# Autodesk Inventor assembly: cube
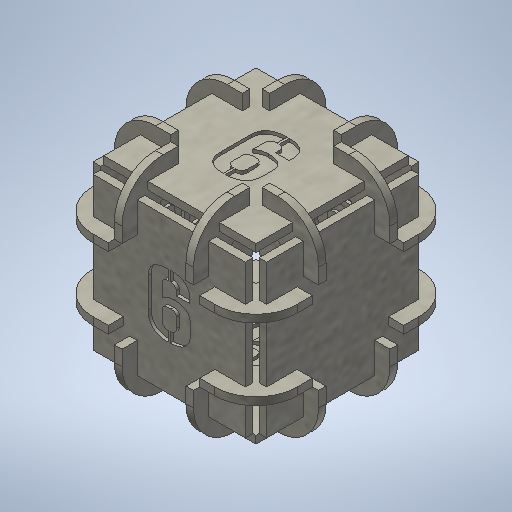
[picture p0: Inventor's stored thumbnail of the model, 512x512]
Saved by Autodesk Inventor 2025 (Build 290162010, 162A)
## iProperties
Created: 2025-02
Part Number: cube
Material: Generisch
Document SubType Name: Assembly
Designer: BennF
Author: BennF
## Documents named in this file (3)
- C:\Users\BennF\OneDrive - Technische Universität Ilmenau\FabAcademy\week03\cube.iam
- C:\Users\BennF\OneDrive - Technische Universität Ilmenau\FabAcademy\week03\square_tile.ipt
- C:\Users\BennF\OneDrive - Technische Universität Ilmenau\FabAcademy\week03\conector_90.ipt
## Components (30 placed, 2 different names)
1. square_tile:1
2. square_tile:2
3. square_tile:3
4. square_tile:4
5. square_tile:5
6. square_tile:6 — Mate:85, Mate:86, Mate:87
7. conector_90:1 — Mate:1, Mate:2, Mate:3
8. conector_90:2 — Mate:4, Mate:5, Mate:6, Mate:34, Mate:35, Mate:36
9. conector_90:3 — Mate:7, Mate:8, Mate:9
10. conector_90:4 — Mate:10, Mate:11, Mate:12, Mate:31, Mate:32, Mate:33
11. conector_90:5 — Mate:13, Mate:14, Mate:15
12. conector_90:6 — Mate:16, Mate:17, Mate:18, Mate:28, Mate:29, Mate:30
13. conector_90:7 — Mate:19, Mate:20, Mate:21
14. conector_90:8 — Mate:22, Mate:23, Mate:24, Mate:25, Mate:26, Mate:27
15. conector_90:9 — Mate:37, Mate:38, Mate:39
16. conector_90:10 — Mate:40, Mate:41, Mate:42
17. conector_90:11 — Mate:43, Mate:44, Mate:45
18. conector_90:12 — Mate:46, Mate:47, Mate:48
19. conector_90:13 — Mate:49, Mate:50, Mate:51
20. conector_90:14 — Mate:52, Mate:53, Mate:54
21. conector_90:15 — Mate:55, Mate:56, Mate:57
22. conector_90:16 — Mate:58, Mate:59, Mate:60
23. conector_90:17 — Mate:61, Mate:62, Mate:63, Mate:85, Mate:86, Mate:87
24. conector_90:18 — Mate:64, Mate:65, Mate:66
25. conector_90:19 — Mate:67, Mate:68, Mate:69
26. conector_90:20 — Mate:70, Mate:71, Mate:72
27. conector_90:21 — Mate:73, Mate:74, Mate:75
28. conector_90:22 — Mate:76, Mate:77, Mate:78
29. conector_90:23 — Mate:79, Mate:80, Mate:81
30. conector_90:24 — Mate:82, Mate:83, Mate:84
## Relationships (87: Mate 87)
- Mate:1: conector_90:1
- Mate:2: conector_90:1
- Mate:3: conector_90:1
- Mate:4: conector_90:2
- Mate:5: conector_90:2
- Mate:6: conector_90:2
- Mate:7: conector_90:3
- Mate:8: conector_90:3
- Mate:9: conector_90:3
- Mate:10: conector_90:4
- Mate:11: conector_90:4
- Mate:12: conector_90:4
- Mate:13: conector_90:5
- Mate:14: conector_90:5
- Mate:15: conector_90:5
- Mate:16: conector_90:6
- Mate:17: conector_90:6
- Mate:18: conector_90:6
- Mate:19: conector_90:7
- Mate:20: conector_90:7
- Mate:21: conector_90:7
- Mate:22: conector_90:8
- Mate:23: conector_90:8
- Mate:24: conector_90:8
- Mate:25: conector_90:8
- Mate:26: conector_90:8
- Mate:27: conector_90:8
- Mate:28: conector_90:6
- Mate:29: conector_90:6
- Mate:30: conector_90:6
- Mate:31: conector_90:4
- Mate:32: conector_90:4
- Mate:33: conector_90:4
- Mate:34: conector_90:2
- Mate:35: conector_90:2
- Mate:36: conector_90:2
- Mate:37: conector_90:9
- Mate:38: conector_90:9
- Mate:39: conector_90:9
- Mate:40: conector_90:10
- Mate:41: conector_90:10
- Mate:42: conector_90:10
- Mate:43: conector_90:11
- Mate:44: conector_90:11
- Mate:45: conector_90:11
- Mate:46: conector_90:12
- Mate:47: conector_90:12
- Mate:48: conector_90:12
- Mate:49: conector_90:13
- Mate:50: conector_90:13
- Mate:51: conector_90:13
- Mate:52: conector_90:14
- Mate:53: conector_90:14
- Mate:54: conector_90:14
- Mate:55: conector_90:15
- Mate:56: conector_90:15
- Mate:57: conector_90:15
- Mate:58: conector_90:16
- Mate:59: conector_90:16
- Mate:60: conector_90:16
- Mate:61: conector_90:17
- Mate:62: conector_90:17
- Mate:63: conector_90:17
- Mate:64: conector_90:18
- Mate:65: conector_90:18
- Mate:66: conector_90:18
- Mate:67: conector_90:19
- Mate:68: conector_90:19
- Mate:69: conector_90:19
- Mate:70: conector_90:20
- Mate:71: conector_90:20
- Mate:72: conector_90:20
- Mate:73: conector_90:21
- Mate:74: conector_90:21
- Mate:75: conector_90:21
- Mate:76: conector_90:22
- Mate:77: conector_90:22
- Mate:78: conector_90:22
- Mate:79: conector_90:23
- Mate:80: conector_90:23
- Mate:81: conector_90:23
- Mate:82: conector_90:24
- Mate:83: conector_90:24
- Mate:84: conector_90:24
- Mate:85: square_tile:6 ↔ conector_90:17
- Mate:86: square_tile:6 ↔ conector_90:17
- Mate:87: square_tile:6 ↔ conector_90:17
